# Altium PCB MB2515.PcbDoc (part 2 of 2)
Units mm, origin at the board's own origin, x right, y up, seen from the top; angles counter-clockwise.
Board outline 43 x 51.45 mm, 4 copper layers (Top Layer, Internal 1, Internal 2, Bottom Layer), stack 1.565 mm thick; 100 components, 89 nets, 374 pads, 852 vias.
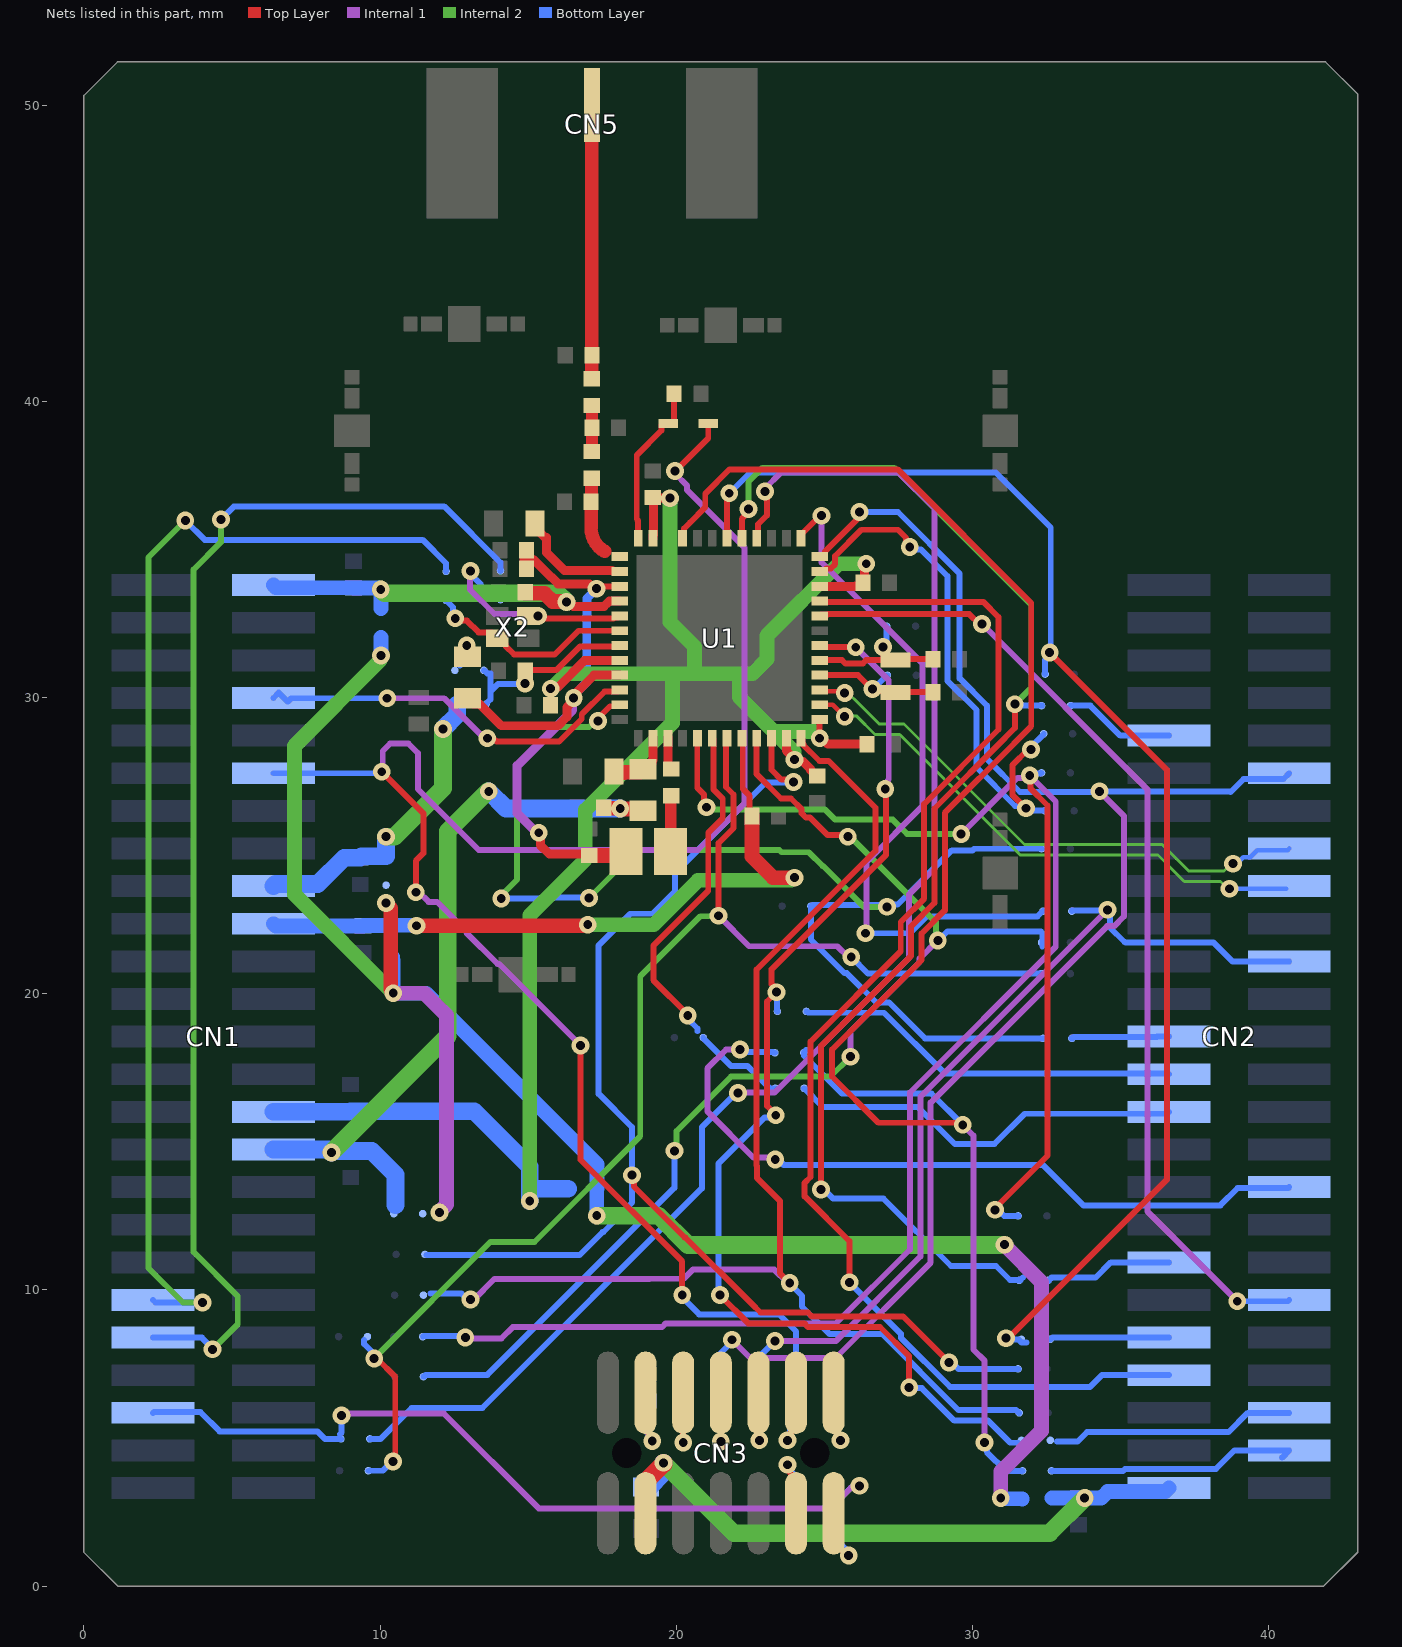
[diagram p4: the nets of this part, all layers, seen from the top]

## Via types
v1: diameter 0.6, hole 0.3, Top Layer to Bottom Layer, tented both sides, 852 vias

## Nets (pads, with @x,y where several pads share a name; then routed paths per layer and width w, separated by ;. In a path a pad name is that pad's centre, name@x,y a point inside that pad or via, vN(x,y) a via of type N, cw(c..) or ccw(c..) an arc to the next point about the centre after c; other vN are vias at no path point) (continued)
GPIO32: CN2.12 R4.2 U1.24 | length 52.4
  Top Layer w0.2: U1.24@24.836,34.753 24.961,34.753 25.011,34.803 25.011,34.925 v1@26.102,36.015
  Internal 1 w0.2: v1(21.88,8.322) 22.497,7.705 25.37,7.705 28.585,10.921 28.585,16.325 34.543,22.283 34.783,22.283 35.105,22.605 35.105,26.007 v1(34.28,26.832)
  Bottom Layer w0.2: R4.2@21.49,7.158 21.49,7.863 21.88,8.253 v1(21.88,8.322) ; v1(26.178,36.264) 27.481,36.264 29.563,34.182 29.563,30.644 30.478,29.729 30.478,27.932 31.6,26.81 34.258,26.81 v1(34.28,26.832) 34.287,26.825 38.68,26.825 38.702,26.802 39.15,27.25 40.496,27.25 CN2.12@40.689,27.443
GPIO33: CN2.29 SB47.1 | length 13.5
  Bottom Layer w0.2: SB47.1@24.311,16.809 24.951,16.17 28.155,16.17 29.4,14.925 30.731,14.925 31.756,15.95 36.562,15.95 CN2.29@36.625,16.013
GPIO34: CN2.41 SB19.2 | length 4
  Bottom Layer w0.2: SB19.2@32.622,8.336 32.634,8.336 32.691,8.393 CN2.41@36.625,8.393
GPIO37: CN1.45 R9.1 SB26.1 | length 27.6
  Internal 1 w0.2: v1(8.7,5.763) 8.762,5.825 12.158,5.825 15.354,2.629 25.199,2.629 25.883,3.313 26.104,3.313 v1(26.18,3.39)
  Bottom Layer w0.2: CN1.45@2.335,5.853 2.365,5.883 3.929,5.883 4.583,5.23 7.879,5.23 8.135,4.973 SB26.1@8.676,4.973 ; 8.645,5.13 8.7,5.185 v1(8.7,5.763) ; R9.1@25.3,2.825 25.395,2.825 25.96,3.39 v1(26.18,3.39)
GPIO38: CN2.22 R5.2 SB33.1 | length 30.1
  Internal 1 w0.2: v1(23.325,8.275) 25.379,8.275 28.235,11.131 28.235,16.513 v1(34.555,22.833)
  Bottom Layer w0.2: R5.2@22.77,7.176 22.814,7.219 22.814,7.763 v1(23.325,8.275) ; SB33.1@33.35,22.8 33.36,22.81 v1@34.432,22.81 ; v1@34.432,22.833 v1(34.555,22.833) 34.632,22.757 34.632,22.237 35.124,21.745 35.141,21.745 35.16,21.725 38.138,21.725 38.769,21.093 CN2.22@40.689,21.093
GPIO39: CN2.25 SB28.1 | length 3.3
  Bottom Layer w0.2: SB28.1@33.35,18.495 33.342,18.503 33.338,18.503 33.35,18.515 33.362,18.503 33.371,18.503 33.41,18.543 36.223,18.543 36.233,18.553 CN2.25@36.625,18.553
GPIO41: CN2.48 SB31.2 | length 8.7
  Bottom Layer w0.2: SB31.2@32.659,3.893 35.079,3.893 35.145,3.96 38.2,3.96 38.21,3.96 38.833,4.583 CN2.48@40.689,4.583 CN2.48@40.447,4.341
GPIO42: CN2.27 SB43.2 | length 13.1
  Bottom Layer w0.2: SB43.2@24.389,19.402 24.401,19.402 24.444,19.359 27.008,19.359 29.056,17.311 36.597,17.311 CN2.27@36.625,17.283
GPIO45: CN2.9 SB24.1 | length 3.7
  Bottom Layer w0.2: SB24.1@33.313,29.725 33.975,29.725 34.987,28.713 CN2.9@36.625,28.713
GPIO46: CN2.34 SB32.2 | length 25.3
  Internal 1 w0.2: v1(22.151,18.114) 21.674,18.114 21.044,17.483 21.044,16.028 22.597,14.475 23.262,14.475 v1(23.337,14.4)
  Bottom Layer w0.2: v1(22.151,18.114) 22.227,18.037 22.465,18.037 22.468,18.035 23.26,18.035 23.276,18.018 23.315,18.018 SB32.2@23.325,18.008 ; v1(23.337,14.4) 23.445,14.4 23.62,14.225 32.368,14.225 33.738,12.855 38.362,12.855 38.947,13.44 40.656,13.44 CN2.34@40.689,13.473
GPIO49: CN2.37 SB29.1 | length 4.3
  Bottom Layer w0.2: SB29.1@32.563,10.325 32.577,10.325 32.667,10.415 34.148,10.415 34.666,10.933 CN2.37@36.625,10.933
GPIO51: CN2.40 U1.20 | length 33.8
  Top Layer w0.2: U1.20@24.836,32.753 24.886,32.803 25.12,32.803 25.128,32.811 29.886,32.811 30.215,32.482 v1(30.32,32.482)
  Internal 1 w0.2: v1(30.32,32.482) 35.9,26.903 35.9,12.653 38.904,9.649 v1@38.921,9.649
  Bottom Layer w0.2: v1(38.934,9.619) 40.645,9.619 CN2.40@40.689,9.663
GPIO54: CN2.43 U1.21 | length 44.5
  Top Layer w0.2: U1.21@24.836,33.253 24.863,33.227 30.361,33.227 30.875,32.712 30.875,28.917 28.363,26.405 28.363,23.212 27.575,22.424 27.575,21.431 24.526,18.382 24.526,13.811 24.331,13.617 24.331,13.161 25.84,11.652 v1(25.84,10.258)
  Bottom Layer w0.2: v1(25.84,10.258) 27.576,8.523 27.576,8.387 29.235,6.728 33.968,6.728 34.363,7.123 CN2.43@36.625,7.123
GPIO55: CN1.8 U1.46 | length 13.4
  Top Layer w0.2: v1(13.619,28.625) 13.695,28.548 13.902,28.548 13.936,28.515 16.045,28.515 16.805,29.276 16.805,29.431 17.578,30.203 18.036,30.203 U1.46@18.086,30.253
  Internal 1 w0.2: v1(10.238,29.975) 12.161,29.975 13.511,28.625 v1(13.619,28.625)
  Bottom Layer w0.2: CN1.8@6.399,29.983 6.578,30.162 6.882,29.857 7,29.975 v1(10.238,29.975)
GPIO56: CN2.46 SB34.2 | length 8.2
  Bottom Layer w0.2: 32.849,4.885 33.543,4.885 33.86,5.202 38.638,5.202 39.29,5.853 CN2.46@40.689,5.853
NetC6_1: C6.1 L4.1 U1.2 | length 2.3
  Top Layer w0.3: L4.1@18.875,27.575 18.975,27.575 19.175,27.775 19.175,27.85 19.211,27.886 U1.2@19.211,28.628
  Top Layer w0.5: C6.1@17.9,27.5 17.95,27.45 17.97,27.47 18.258,27.47 18.263,27.475 18.775,27.475 L4.1@18.875,27.575
NetC7_2: C7.2 D1.1 U1.36 | length 5.6
  Top Layer w0.2: U1.36@18.711,35.378 18.711,35.968 18.661,36.018 18.661,38.18 19.5,39.019 19.5,39.194 19.55,39.244 19.875,39.244 19.925,39.294 C7.2@19.925,40.25
NetC8_1: C8.1 SB38.1 U1.16 X1.2 | length 4.8
  Top Layer w0.2: U1.16@24.836,30.753 26.132,30.753 26.6,30.285 v1(26.62,30.285) ; v1@26.61,30.275 26.66,30.225 27.337,30.225 X1.2@27.398,30.165 ; X1.2@27.398,30.1 X1.2@27.5,30.1 ; X1.2@27.5,30.18 C8.1@28.66,30.18
  Bottom Layer w0.2: v1(26.62,30.285) 26.645,30.285 27.11,30.75 SB38.1@27.125,30.75
NetC9_2: C9.2 SB37.1 U1.17 X1.1 | length 5.3
  Top Layer w0.2: U1.17@24.836,31.253 24.842,31.259 25.592,31.259 25.703,31.148 26.295,31.148 26.406,31.259 X1.1@27.231,31.259 ; v1(26.974,31.702) 26.998,31.679 26.998,31.415 27.153,31.259 X1.1@27.231,31.259 ; C9.2@28.663,31.295 27.428,31.295 27.392,31.259 X1.1@27.231,31.259
  Bottom Layer w0.2: v1(26.974,31.702) 26.974,31.811 27.098,31.935 SB37.1@27.098,32.407
NetC11_2: C11.2 U1.38 | length 3.9
  Top Layer w0.3: C11.2@15.225,35.875 15.225,35.75 15.581,35.394 15.619,35.394 15.619,34.89 16.219,34.29 17.836,34.29 17.873,34.253 U1.38@18.086,34.253
NetC12_1: C12.1 L1.1 U1.37 | length 2.6
  Top Layer w0.45: L1.1@17.15,37.4 17.15,37.385 17.135,37.37 17.135,36.619 C12.1@17.121,36.605 17.121,35.722 ccw(c18.033,35.722) 17.577,34.932
NetC13_2: C13.2 L1.2 L2.1 | length 1.6
  Top Layer w0.4: L2.1@17.145,39.858 17.147,39.856 17.147,39.102 C13.2@17.15,39.1 L1.2@17.15,38.3
NetC14_1: C14.1 CN5.1 L2.2 | length 9.2
  Top Layer w0.45: L2.2@17.145,40.758 17.147,40.761 17.147,41.548 C14.1@17.15,41.55 17.145,41.555 17.145,49.98 17.145,49.995 CN5.1@17.15,50
NetC15_1: C15.1 SB6.2 SB41.1 U1.43 | length 6.6
  Top Layer w0.2: v1(14.891,30.475) 14.896,30.479 14.896,30.899 14.922,30.925 15.95,30.925 16.75,31.725 18.058,31.725 U1.43@18.086,31.753
  Bottom Layer w0.2: SB41.1@13.501,30.917 13.515,30.917 13.615,30.817 13.72,30.817 13.72,30.195 ; SB6.2@13.575,29.775 13.575,29.785 13.72,29.93 13.72,30.195 ; v1(14.891,30.475) 14.878,30.462 13.987,30.462 13.72,30.195
NetC23_2: C23.2 C24.1 C26.1 L6.2 L7.1 U1.39 U1.45 | length 24.2
  Top Layer w0.2: C26.1@14.942,34.351 14.81,34.482 14.81,34.665 ; C24.1@14.942,34.976 14.81,34.844 14.81,34.665 ; 15.168,34.665 14.81,34.665 ; v1(17.308,33.673) 17.416,33.673 17.497,33.753 U1.39@18.086,33.753
  Top Layer w0.3: L7.1@12.95,29.975 13.15,29.775 13.358,29.775 14.086,29.046 16.01,29.046 16.305,29.341 16.305,29.671 16.533,29.899 v1(16.533,29.98) ; 15.168,34.665 15.763,34.07 15.772,34.07 16.005,33.837 17.063,33.837 17.227,33.673 v1(17.308,33.673) ; v1(15.354,25.433) 15.411,25.375 15.411,25.019 15.716,24.714 17.005,24.714 C23.2@17.053,24.666 ; v1@16.489,30.024 17.218,30.753 U1.45@18.086,30.753
  Top Layer w0.5: C23.2@17.053,24.666 18.166,24.666 L6.2@18.3,24.8
  Internal 1 w0.3: v1(15.354,25.433) 15.291,25.433 14.626,26.097 14.626,27.701 16.495,29.57 16.495,29.942 v1(16.533,29.98)
  Bottom Layer w0.3: v1(16.533,29.98) 16.533,30.068 16.975,30.51 16.975,32.773 16.977,32.775 16.977,33.342 v1(17.308,33.673)
NetCN3_4: CN3.4 R2.1 | length 3.2
  Top Layer w0.2: CN3.4@18.96,6.532 19.061,6.431 19.061,5.13 19.184,5.007 v1(19.184,4.902)
  Bottom Layer w0.2: R2.1@18.975,6.258 18.944,6.227 18.944,5.248 19.184,5.007 v1(19.184,4.902)
NetCN3_6: CN3.6 R3.1 | length 3.1
  Top Layer w0.2: v1(20.23,4.85) CN3.6@20.23,6.532
  Bottom Layer w0.2: R3.1@20.211,6.276 20.23,6.257 v1(20.23,4.85)
NetCN3_8: CN3.8 R4.1 | length 3
  Top Layer w0.2: v1(21.5,4.885) CN3.8@21.5,6.532
  Bottom Layer w0.2: R4.1@21.49,6.258 21.5,6.248 v1(21.5,4.885)
NetCN3_10: CN3.10 R5.1 | length 3
  Top Layer w0.2: CN3.10@22.77,6.532 22.785,6.517 22.785,4.94 v1(22.8,4.925)
  Bottom Layer w0.2: R5.1@22.77,6.276 22.8,6.246 v1(22.8,4.925)
NetCN3_11: CN3.11 R6.2 | length 3.1
  Top Layer w0.2: v1(23.755,4.1) 23.83,4.025 23.83,3.841 23.939,3.732 23.939,2.564 CN3.11@24.04,2.462
  Bottom Layer w0.2: v1(23.755,4.1) 23.755,3.994 24.018,3.731 R6.2@24.018,2.875
NetCN3_12: CN3.12 R7.1 | length 3.2
  Top Layer w0.2: v1(23.755,4.925) 23.83,5 23.83,5.153 24.04,5.364 CN3.12@24.04,6.532
  Bottom Layer w0.2: v1(23.755,4.925) 23.83,5 23.83,5.438 24.037,5.645 24.037,6.255 R7.1@24.04,6.258
NetCN3_13: CN3.13 R9.2 | length 2.8
  Top Layer w0.2: CN3.13@25.31,2.462 25.31,1.491 25.762,1.039 v1(25.815,1.039)
  Bottom Layer w0.2: R9.2@25.3,1.925 25.395,1.925 25.545,1.775 25.545,1.415 25.815,1.144 v1(25.815,1.039)
NetCN3_14: CN3.14 R8.1 | length 3.1
  Top Layer w0.2: CN3.14@25.31,6.532 25.411,6.431 25.411,5.157 25.538,5.031 v1(25.538,4.925)
  Bottom Layer w0.2: R8.1@25.31,6.258 25.31,5.259 25.538,5.031 v1(25.538,4.925)
NetL5_1: L5.1 U1.3 | length 1
  Top Layer w0.2: L5.1@19.674,27.596 L5.1@19.711,27.633
  Top Layer w0.3: L5.1@19.711,27.633 U1.3@19.711,28.628
NetL5_2: L5.2 L6.1 | length 1.9
  Top Layer w0.4: L6.1@19.8,24.8 19.812,24.812 19.812,26.671 L5.2@19.824,26.683
NetL7_2: L7.2 SB41.2 | length 1.2
  Top Layer w0.2: v1(12.923,31.757) 12.923,31.402 L7.2@12.95,31.375
  Bottom Layer w0.2: 12.702,31.075 12.702,31.44 12.923,31.661 v1(12.923,31.757)
NetSB1_1: SB1.1 SB2.1 SB3.1 SB4.1 SB5.1 SB36.1 | length 63.4
  Top Layer w0.5: v1(10.2,23.064) 10.2,23.036 10.358,22.879 10.358,20.133 10.444,20.046 v1(10.444,20.019)
  Internal 1 w0.5: v1(10.444,20.019) 10.447,20.017 11.494,20.017 11.86,19.651 12.24,19.271 12.24,12.882 12.001,12.643 v1(12.001,12.616) ; v1(30.95,2.975) 30.95,3.869 32.325,5.244 32.325,10.258 v1@31.079,11.505
  Internal 2 w0.5: v1(10.025,31.415) 10.006,31.396 10.006,31.258 7.11,28.363 7.11,23.353 v1(10.444,20.019)
  Internal 2 w0.6: v1(17.312,12.508) 19.405,12.508 20.395,11.519 31.069,11.519 v1(31.079,11.529)
  Bottom Layer w0.5: v1(10.025,31.415) SB2.1@10.025,32.025 ; 10.413,21.235 10.413,21.154 10.444,21.122 v1(10.444,20.019) 11.547,20.019 17.32,14.247 SB4.1@17.32,13.419 17.31,13.41 17.31,12.554 17.312,12.552 v1(17.312,12.508) ; v1(30.95,2.975) 30.969,2.956 31.664,2.956 SB36.1@31.675,2.945
NetSB7_2: SB7.2 SB8.2 U1.10 | length 44
  Top Layer w0.2: v1(18.5,13.875) 18.564,13.811 18.564,13.49 20.28,11.774 20.304,11.774 22.54,9.538 22.841,9.237 24.444,9.237 24.582,9.099 27.64,9.099 27.649,9.109 v1@29.201,7.558 ; U1.10@23.211,28.628 23.211,27.56 23.543,27.228 23.872,27.228 v1(23.949,27.152)
  Bottom Layer w0.2: SB8.2@11.563,11.175 16.728,11.175 17.511,11.958 17.54,11.958 17.862,12.28 17.862,12.31 18.5,12.947 v1(18.5,13.875) 18.5,15.496 17.375,16.621 17.375,21.635 18.441,22.701 19.204,22.701 19.946,23.444 19.946,24.062 23.017,27.133 23.93,27.133 v1(23.949,27.152) ; v1(29.201,7.548) 29.309,7.548 29.518,7.339 SB7.2@31.55,7.339
NetSB9_2: SB9.2 SB12.2 SB21.2 U1.5 | length 67.7
  Top Layer w0.2: U1.5@20.711,28.628 20.704,28.621 20.704,26.951 20.939,26.716 20.939,26.373 v1(21.016,26.297) ; v1(30.756,12.705) 30.756,12.759 32.53,14.533 32.53,26.353 31.948,26.935 31.948,27.346 v1(31.93,27.365)
  Internal 1 w0.2: v1(12.875,8.393) 12.908,8.36 14.091,8.36 14.476,8.746 19.513,8.746 19.639,8.872 25.39,8.872 27.885,11.367 27.885,16.664 32.805,21.584 32.805,26.49 v1(31.93,27.365) 31.853,27.288 31.51,27.288 v1(29.613,25.391)
  Internal 2 w0.2: v1(21.016,26.297) 21.087,26.225 25.012,26.225 25.36,25.878 27.303,25.878 27.789,25.391 v1(29.613,25.391)
  Bottom Layer w0.2: SB9.2@11.439,8.425 11.45,8.425 11.467,8.442 12.826,8.442 v1(12.875,8.393) ; v1(30.756,12.705) 30.862,12.705 31.067,12.5 SB12.2@31.55,12.5 ; v1(31.93,27.365) 32.005,27.439 32.295,27.439 32.314,27.458 SB21.2@32.326,27.458
NetSB10_1: SB10.1 SB13.1 U1.23 | length 18.8
  Top Layer w0.2: U1.23@24.836,34.253 24.961,34.253 25.061,34.353 25.215,34.353 25.361,34.5 25.361,34.778 26.244,35.661 27.481,35.661 27.752,35.391 27.752,35.073 v1@27.775,35.05 ; v1(31.798,26.26) 31.793,26.26 31.35,26.703 31.35,27.725 31.87,28.245 v1(31.971,28.245)
  Bottom Layer w0.2: v1(27.876,35.077) 27.952,35.001 28.249,35.001 29.149,34.101 29.149,30.564 30.128,29.584 30.128,27.641 31.433,26.337 31.722,26.337 v1(31.798,26.26) 31.875,26.184 32.375,26.184 32.427,26.183 SB10.1@32.438,26.173 ; v1(31.971,28.245) 31.971,28.333 32.401,28.763 SB13.1@32.401,28.775
NetSB14_2: SB14.2 SB17.2 U1.9 | length 39.3
  Top Layer w0.2: U1.9@22.711,28.628 22.711,27.411 23.533,26.59 23.868,26.59 24.227,26.231 24.227,26.092 24.374,25.945 24.513,25.945 25.107,25.352 25.736,25.352 v1(25.787,25.301)
  Internal 1 w0.2: v1(25.875,17.875) 25.875,18.733 28.208,21.066 28.208,21.183 v1(28.825,21.8)
  Internal 2 w0.2: v1(19.932,14.697) 20.006,14.771 20.006,15.362 21.848,17.204 25.204,17.204 v1(25.875,17.875) ; v1(25.787,25.301) 25.874,25.301 28.76,22.415 28.76,21.865 v1(28.825,21.8)
  Bottom Layer w0.2: SB14.2@11.463,7.076 11.478,7.076 11.535,7.134 13.619,7.134 19.932,13.447 v1(19.932,14.697) ; v1@28.837,21.787 29.149,22.099 32.305,22.099 32.35,22.054 32.35,21.6
NetSB16_2: SB16.2 SB18.2 U1.12 | length 44.3
  Top Layer w0.2: v1(23.827,10.235) 23.493,10.569 23.493,13.01 22.728,13.775 22.728,14.189 22.711,14.206 22.711,20.818 26.719,24.825 26.719,26.277 25.141,27.855 24.828,27.855 24.286,28.397 24.286,28.428 24.261,28.453 24.261,28.578 U1.12@24.211,28.628
  Internal 1 w0.2: v1(13.05,9.675) 13.158,9.675 13.86,10.377 19.099,10.377 19.101,10.38 20.249,10.38 20.555,10.686 23.305,10.686 23.755,10.235 v1(23.827,10.235)
  Bottom Layer w0.2: 11.705,9.875 12.744,9.875 12.944,9.675 v1(13.05,9.675) ; v1(23.827,10.235) 23.827,10.218 24.243,9.802 24.243,9.438 25.164,8.517 26.948,8.517 29.523,5.943 31.47,5.943 31.56,5.853 SB18.2@31.572,5.853
NetSB19_1: SB19.1 SB22.1 U1.30 | length 46.3
  Top Layer w0.2: U1.30@21.711,35.378 21.711,36.822 v1(21.784,36.895) ; v1(31.129,8.374) 31.199,8.374 36.565,13.74 36.565,27.55 v1(32.6,31.515)
  Bottom Layer w0.2: v1@21.795,36.895 22.5,37.6 30.774,37.6 32.637,35.737 32.637,31.552 v1(32.6,31.515) 32.6,31.424 32.439,31.263 SB22.1@32.439,30.79 ; v1(31.129,8.374) 31.17,8.332 31.543,8.332 31.645,8.23 31.823,8.23
NetSB23_2: SB23.2 SB28.2 SB30.2 U1.47 | length 42.6
  Top Layer w0.2: v1(17.355,29.203) 17.355,29.301 17.758,29.703 18.036,29.703 U1.47@18.086,29.753
  Internal 2 w0.2: v1(14.089,23.213) 14.089,23.317 14.626,23.854 14.626,27.701 15.931,29.006 17.05,29.006 17.247,29.203 v1(17.355,29.203) ; v1(17.053,23.234) 18.67,24.851 23.472,24.851 23.546,24.776 24.471,24.776 24.937,24.31 24.953,24.31 26.329,22.933 v1(27.11,22.933)
  Bottom Layer w0.2: v1(14.089,23.213) 14.094,23.208 15.526,23.208 ; 15.526,23.248 17.039,23.248 v1(17.053,23.234) ; SB23.2@32.348,24.894 30.055,24.894 30.002,24.841 29.298,24.841 27.467,23.01 27.187,23.01 v1(27.11,22.933) 27.043,23.001 24.599,23.001 24.558,22.96 SB30.2@24.543,22.96 24.543,21.825 25.674,20.695 25.752,20.695 26.737,19.709 27.175,19.709 28.39,18.495 SB28.2@32.375,18.495
NetSB24_2: SB24.2 SB29.2 U1.29 | length 45.4
  Top Layer w0.2: U1.29@22.211,35.378 22.211,36.03 22.436,36.255 v1(22.436,36.361) ; v1(24.881,13.389) 24.881,17.445 24.876,17.451 24.876,18.229 27.925,21.278 27.925,22.279 28.713,23.067 28.713,26.25 31.071,28.608 31.071,28.618 31.425,28.972 v1(31.425,29.775)
  Internal 2 w0.2: v1(22.436,36.361) 22.436,37.283 22.903,37.75 27.35,37.75 31.98,33.12 31.98,30.33 v1(31.425,29.775)
  Bottom Layer w0.2: v1(24.881,13.389) 24.99,13.389 25.293,13.085 26.991,13.085 29.269,10.807 30.786,10.807 31.259,10.335 31.578,10.335 31.588,10.325 31.602,10.325 31.702,10.425 ; v1(31.425,29.775) 31.467,29.733 32.329,29.733 SB24.2@32.338,29.725
NetSB26_2: SB26.2 U1.28 | length 50
  Top Layer w0.2: U1.28@22.711,35.378 22.756,35.423 22.756,35.847 23.053,36.144 23.053,36.894 v1(22.991,36.955)
  Internal 1 w0.2: v1(22.075,16.654) 22.09,16.668 23.316,16.668 27.858,21.211 27.858,23.355 28.713,24.21 28.713,36.387 27.51,37.59 23.528,37.59 22.991,37.053 v1(22.991,36.955)
  Bottom Layer w0.2: SB26.2@9.651,4.973 10.018,4.973 11.063,6.018 13.449,6.018 20.861,13.43 20.861,15.494 22.021,16.654 v1(22.075,16.654)
NetSB31_1: SB31.1 SB32.1 U1.33 | length 58.3
  Top Layer w0.2: U1.33@20.211,35.378 20.261,35.428 20.261,35.707 20.458,35.903 20.459,35.903 20.975,36.419 20.975,36.88 21.795,37.7 27.47,37.7 31.98,33.19 31.98,29.032 31.421,28.473 31.421,28.463 29.063,26.105 29.063,22.816 28.275,22.028 28.275,21.133 25.254,18.112 25.254,17.206 26.816,15.645 29.595,15.645 v1(29.665,15.575)
  Internal 1 w0.2: v1(29.665,15.575) 30.025,15.215 30.025,7.992 30.404,7.613 v1(30.404,4.85)
  Bottom Layer w0.2: SB32.1@24.375,18.097 24.3,18.022 SB32.1@24.3,18.008 24.31,17.997 24.31,17.907 25.584,16.634 28.606,16.634 v1(29.665,15.575) ; v1(30.404,4.85) 30.478,4.775 30.478,4.528 31.113,3.893 SB31.1@31.684,3.893
NetSB33_2: SB33.2 U1.25 | length 23.7
  Top Layer w0.2: U1.25@24.211,35.378 24.211,35.503 24.846,36.138 v1(24.9,36.138)
  Internal 1 w0.2: v1(24.9,36.138) 24.9,34.561 28.302,31.16 28.302,26.329 26.421,24.449 26.421,22.083 v1(26.38,22.043)
  Bottom Layer w0.2: v1(26.38,22.043) 27.886,22.043 28.457,22.614 32.189,22.614 SB33.2@32.375,22.8
NetSB34_1: SB34.1 SB43.1 U1.18 | length 39.9
  Top Layer w0.2: v1(21.471,9.83) 21.471,9.827 22.426,8.872 24.314,8.872 24.437,8.749 26.876,8.749 27.858,7.767 v1(27.858,6.708) ; v1(23.353,15.9) 23.353,15.926 23.061,16.217 23.061,19.736 23.375,20.049 23.375,20.161 23.217,20.319 23.217,20.828 27.069,24.68 27.069,26.89 v1(27.05,26.909) ; U1.18@24.836,31.753 24.884,31.706 v1@26.048,31.706
  Internal 1 w0.2: v1(26.056,31.698) 27.17,30.584 27.17,27.226 27.127,27.183 27.127,26.985 v1(27.05,26.909)
  Bottom Layer w0.2: v1(21.471,9.83) 21.425,9.876 21.425,14.274 22.978,15.827 23.279,15.827 v1(23.353,15.9) ; v1(23.375,20.053) 23.401,20.027 23.401,19.415 SB43.1@23.414,19.402 ; v1(27.858,6.708) 27.88,6.686 28.284,6.686 29.382,5.589 30.522,5.589 31.267,4.844 31.541,4.844
NetSB39_1: SB39.1 U1.42 X2.1 | length 7.2
  Top Layer w0.2: v1(12.535,32.672) 12.612,32.596 12.929,32.596 13.325,32.2 13.75,32.2 X2.1@13.95,32 14.025,32 14.225,31.8 14.225,31.746 14.521,31.45 15.891,31.45 16.694,32.253 U1.42@18.086,32.253
  Bottom Layer w0.2: SB39.1@12.225,33.282 12.461,33.046 12.461,32.747 v1(12.535,32.672)
NetSB40_1: SB40.1 U1.41 X2.3 | length 7.6
  Top Layer w0.2: v1(15.324,32.75) 15.401,32.673 15.637,32.673 15.641,32.669 17.877,32.669 17.911,32.703 18.036,32.703 U1.41@18.086,32.753
  Internal 1 w0.2: v1(13.051,34.27) 13.035,34.254 13.035,33.642 13.862,32.816 15.258,32.816 v1(15.324,32.75)
  Bottom Layer w0.2: v1(13.051,34.27) 13.051,34.161 13.41,33.802 13.41,33.737 13.682,33.465 13.883,33.465 14.048,33.3 SB40.1@14.063,33.3
NetSB44_2: SB44.2 SB45.2 SB48.2 U1.7 | length 44.6
  Top Layer w0.2: v1(9.798,7.689) 9.893,7.689 10.509,7.073 10.509,4.285 v1(10.434,4.21) ; v1(21.425,22.632) 21.426,25.088 21.927,25.59 21.927,26.725 21.674,26.978 21.674,28.591 U1.7@21.711,28.628
  Internal 1 w0.2: v1(21.425,22.632) 22.453,21.604 25.434,21.604 25.793,21.245 v1(25.901,21.245)
  Internal 2 w0.2: v1(9.798,7.689) 9.798,7.697 13.721,11.621 15.209,11.621 18.78,15.191 18.78,20.586 20.81,22.616 21.409,22.616 v1(21.425,22.632)
  Bottom Layer w0.2: 9.457,8.314 9.457,8.18 9.798,7.839 v1(9.798,7.689) ; SB44.2@9.604,3.898 10.094,3.898 10.406,4.21 v1(10.434,4.21) ; v1(25.901,21.245) 26.468,20.678 SB48.2@32.311,20.678
NetSB46_2: SB46.2 SB47.2 U1.6 | length 14.8
  Top Layer w0.2: v1(20.384,19.265) 20.384,19.297 19.221,20.461 19.221,21.62 21.076,23.475 21.076,25.435 21.566,25.925 21.566,26.584 21.25,26.9 21.25,28.59 U1.6@21.211,28.628
  Bottom Layer w0.2: v1(20.384,19.265) 20.384,19.157 20.713,18.829 20.713,18.735 ; SB46.2@20.907,18.52 20.907,18.495 21.838,17.564 22.398,17.564 23.152,16.809 SB47.2@23.336,16.809
NRST: CN1.12 D1.2 R7.2 | length 62
  Top Layer w0.2: v1(10.054,27.493) 11.46,26.087 11.46,24.743 11.205,24.488 v1(11.205,23.425) ; v1(16.766,18.257) 16.766,14.397 20.196,10.967 v1(20.196,9.83) ; v1(19.951,37.65) 19.974,37.65 21.075,38.751 D1.2@21.075,39.244
  Internal 1 w0.2: v1(10.054,27.493) 10.087,27.527 10.087,28.193 10.338,28.444 10.954,28.444 11.276,28.122 11.276,26.904 13.329,24.851 20.729,24.851 22.304,26.426 22.304,35.055 20.361,36.997 20.361,37.149 19.951,37.56 v1(19.951,37.65) ; v1(11.205,23.425) 11.313,23.425 11.637,23.102 11.92,23.102 12.907,22.116 12.907,22.061 13.961,21.007 14.015,21.007 v1(16.766,18.257)
  Bottom Layer w0.2: CN1.12@6.399,27.443 10.004,27.443 v1(10.054,27.493) ; v1(20.196,9.83) 20.196,9.75 20.769,9.177 23.466,9.177 24.04,8.603 R7.2@24.04,7.158
OSC_IN: CN1.39 SB39.2 | length 39.4
  Internal 2 w0.2: v1(3.425,35.975) 2.175,34.725 2.175,10.743 3.343,9.575 v1(4,9.575)
  Bottom Layer w0.2: CN1.39@2.335,9.663 2.423,9.575 v1(4,9.575) ; v1(3.425,35.975) 4.08,35.32 11.435,35.32 12.225,34.53 SB39.2@12.225,34.257
OSC_OUT: CN1.41 SB40.2 | length 42.3
  Internal 2 w0.2: v1(4.345,7.996) 5.193,8.844 5.193,9.793 3.7,11.286 3.7,34.315 4.624,35.24 v1(4.624,36.008)
  Bottom Layer w0.2: CN1.41@2.335,8.393 3.982,8.393 4.354,8.022 4.354,8.005 v1(4.345,7.996) ; v1(4.624,36.008) 5.057,36.441 5.181,36.441 5.193,36.452 12.162,36.452 14.063,34.552 SB40.2@14.063,34.275
USB_FS_N: CN2.18 U1.14 | length 18.3
  Top Layer w0.155: U1.14@24.836,29.753 25.282,29.753 v1(25.68,29.355)
  Internal 2 w0.1: v1(25.68,29.355) 25.708,29.383 26.071,29.383 26.702,28.752 27.536,28.752 31.604,24.684 36.255,24.684 37.147,23.792 38.371,23.792 38.62,23.543 v1(38.675,23.543)
  Bottom Layer w0.155: v1(38.675,23.543) CN2.18@40.59,23.543
USB_FS_P: CN2.16 U1.15 | length 18.7
  Top Layer w0.155: U1.15@24.836,30.253 24.885,30.204 25.631,30.204 v1(25.68,30.155)
  Internal 2 w0.1: v1(25.68,30.155) 25.794,30.155 26.136,29.813 26.847,29.102 27.681,29.102 31.749,25.034 36.4,25.034 37.292,24.142 38.488,24.142 38.738,24.391 v1(38.793,24.391)
  Bottom Layer w0.155: v1(38.793,24.391) 38.913,24.391 39.134,24.612 39.37,24.612 39.603,24.845 40.631,24.845 CN2.16@40.689,24.903
VDD1: C2.2 C10.1 CN1.2 SB2.2 U1.40 | length 14.3
  Top Layer w0.2: U1.40@18.075,33.242 U1.40@18.086,33.253 U1.40@18.081,33.248
  Top Layer w0.3: v1(16.294,33.223) 16.375,33.223 16.525,33.073 17.557,33.073 17.687,33.203 17.692,33.203 17.742,33.253 U1.40@18.081,33.253
  Top Layer w0.5: C10.1@14.9,33.55 14.9,33.525 14.905,33.52 15.544,33.52 15.822,33.242 16.275,33.242 v1(16.294,33.223)
  Internal 2 w0.6: v1(10.022,33.641) 10.143,33.52 15.997,33.52 v1(16.294,33.223)
  Bottom Layer w0.5: CN1.2@6.399,33.793 6.487,33.705 9.095,33.705 9.105,33.695 9.94,33.695 9.995,33.641 v1(10.022,33.641) ; SB2.2@10.025,33 v1@10.025,33.637
VDD3: C3.2 CN1.18 SB3.2 SB6.1 | length 10.5
  Internal 2 w0.6: v1(10.2,25.301) 10.485,25.301 12.119,26.935 v1(12.119,28.933)
  Bottom Layer w0.6: CN1.18@6.399,23.633 6.468,23.702 7.896,23.702 8.786,24.592 C3.2@9.329,24.592 9.375,24.638 SB3.2@10.2,24.638 v1(10.2,25.301) ; v1(12.119,28.933) 12.6,29.414 SB6.1@12.6,29.775
VDD4: C4.2 C16.1 C17.1 C18.1 C19.1 C28.1 CN1.30 SB4.2 U1.11 U1.13 U1.22 U1.35 U1.44 | length 66.5
  Top Layer w0.2: v1(24.836,28.625) U1.13@24.836,29.253
  Top Layer w0.3: v1@16.007,30.355 16.905,31.253 U1.44@18.086,31.253 ; U1.35@19.211,35.378 19.211,35.458 19.228,35.475 19.228,36.753 19.241,36.74 19.77,36.74 v1(19.781,36.729) ; U1.11@23.711,28.628 23.711,28.202 23.985,27.928 v1(23.985,27.901) ; v1@24.271,27.843 24.523,27.591 24.523,27.559 24.732,27.35 C16.1@24.757,27.35 ; v1(24.836,28.625) 24.917,28.625 25.116,28.426 C28.1@26.434,28.426 ; U1.22@24.836,33.753 26.019,33.753 26.036,33.77 26.195,33.77 C17.1@26.3,33.875 26.355,33.93 26.355,34.458 v1(26.41,34.513)
  Internal 2 w0.2: v1(15.755,30.298) v1@15.802,30.298
  Internal 2 w0.5: v1(15.051,13) 15.051,22.65 16.927,24.526 16.927,26.197 19.87,29.141 19.87,30.802 ; v1@15.802,30.298 15.802,30.317 16.286,30.802 19.87,30.802 ; v1(19.781,36.729) 19.781,32.552 20.614,31.718 20.614,30.802 ; v1(23.985,27.901) 23.966,27.92 23.966,28.176 23.289,28.853 ; v1(24.836,28.625) 24.836,28.652 24.673,28.816 24.673,28.853 23.289,28.853 ; v1(26.41,34.513) 25.478,34.513 23.059,32.094 23.059,31.286 22.574,30.802 22.131,30.802 ; 19.87,30.802 20.614,30.802 ; 20.614,30.802 22.131,30.802 ; 22.131,30.802 22.131,30.011 23.289,28.853
  Bottom Layer w0.6: CN1.30@6.399,16.013 8.978,16.013 C4.2@9.001,16.036 13.175,16.036 15.05,14.161 v1(15.051,13) ; 15.184,13.419 SB4.2@16.345,13.419
VDD5: C5.2 C21.1 CN1.32 L4.2 SB5.2 | length 26.1
  Top Layer w0.5: C21.1@17.55,26.275 17.55,26.268 17.555,26.263 v1@18.092,26.263 ; v1(18.104,26.25) v1@18.092,26.263 ; L4.2@18.875,26.175 18.819,26.231 18.123,26.231 v1@18.092,26.263
  Internal 2 w0.6: v1(8.355,14.642) 12.284,18.571 12.284,25.481 13.635,26.832 v1(13.665,26.832)
  Bottom Layer w0.6: CN1.32@6.399,14.743 8.355,14.743 v1(8.355,14.642) 8.402,14.689 C5.2@9.005,14.689 ; C5.2@9.018,14.692 9.719,14.692 10.521,13.89 10.521,12.866 ; v1(13.665,26.832) 14.247,26.25 v1(18.104,26.25)
VDD14: C22.2 C27.2 CN2.49 CN3.3 SB36.2 | length 22.9
  Top Layer w0.6: CN3.3@18.96,2.462 18.96,3.525 19.561,4.126 v1(19.561,4.166)
  Internal 2 w0.6: v1(19.561,4.166) 21.938,1.789 32.591,1.789 v1(33.782,2.98)
  Bottom Layer w0.5: SB36.2@32.681,2.975 C27.2@33.575,2.975 33.58,2.98 34.341,2.98 34.555,3.195 36.507,3.195 CN2.49@36.625,3.313
  Bottom Layer w0.6: C22.2@18.975,3.35 19.1,3.35 19.561,3.811 v1(19.561,4.166)
VDDA: C1.2 C20.2 CN1.20 SB1.2 U1.8 | length 24.2
  Top Layer w0.2: U1.8@22.211,28.628 22.239,28.6 22.239,26.915 22.472,26.682 22.472,26.078 C20.2@22.55,26
  Top Layer w0.5: v1(11.229,22.293) 16.942,22.293 16.98,22.331 v1(17.007,22.331) ; C20.2@22.55,26 22.555,25.995 22.555,24.629 23.266,23.918 v1(23.992,23.918)
  Internal 2 w0.5: v1@17.034,22.331 19.236,22.331 20.733,23.829 23.875,23.829 23.965,23.918 v1(23.992,23.918)
  Bottom Layer w0.5: CN1.20@6.399,22.363 6.474,22.288 9.417,22.288 9.427,22.298 10.348,22.298 SB1.2@10.413,22.364 10.464,22.312 11.21,22.312 v1(11.229,22.293)
pads on no net: CN1.3 CN1.4 CN1.5 CN1.10 CN1.11 CN1.16 CN1.19 CN1.21 CN1.23 CN1.27 CN1.43 CN1.48 CN1.50 CN2.1 CN2.3 CN2.4 CN2.5 CN2.6 CN2.17 CN2.19 CN2.24 CN2.28 CN2.30 CN2.31 CN2.33 CN2.36 CN2.47 CN3.1 CN3.2 CN3.9 CN3.NPTH1 CN3.NPTH2 U1.19 U1.31 U1.32 U1.48

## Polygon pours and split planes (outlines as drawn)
GND on Bottom Layer "Bottom Layer-GND" (solid, remove dead copper, pour order 7): -5.722,60.183 47.45,60.183 47.45,-6.633 -5.722,-6.633
GND on Top Layer "Top Layer-GND" (solid, remove dead copper, pour order 9): -0.984,56.842 44.025,56.842 44.025,-1.8 -0.984,-1.8
GND on Internal 2 "Internal 2-GND" (solid, remove dead copper, pour order 11): -6.863,54.407 46.703,54.407 46.703,-2.025 -6.863,-2.025
GND on Internal 1 "GND_L02_P016" (solid, remove dead copper, pour order 16): 18.5,52.219 18.5,34.43 15.86,34.43 15.86,52.219 -1.639,52.219 -1.639,-2.225 44.069,-2.225 45.097,-0.949 45.097,-0.533 45.097,52.219

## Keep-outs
Top Layer:
  rectangle: 16.907,40.223 17.392,40.384
  rectangle: 16.912,37.765 17.397,37.926
  rectangle: 18.61,29.16 24.299,34.848
Keep-Out Layer:
  lines w0.1: 43.001,1.145 43.001,39.986 43.001,50.374 41.925,51.45 1.127,51.45 0.001,50.324 0.001,1.143 1.139,0.005 41.852,0.005 42.505,0.652 43.002,1.145

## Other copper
Top Layer:
  region net NetC12_1: 17.699,35.121 18.079,34.903 18.361,34.903 18.361,34.603 17.811,34.603 17.498,34.721 17.489,34.724
  text "1" at 10.365,1.475 h0.81
Internal 1:
  text "2" at 10.91,1.475 h0.81
Internal 2:
  text "3" at 11.59,1.484 h0.81
Bottom Layer:
  text "4" at 12.616,1.475 h0.81
Multi-Layer:
  pour cut-out: 10.149,2.2 10.147,1.375 12.802,1.375 12.802,2.2

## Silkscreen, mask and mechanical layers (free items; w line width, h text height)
Top Overlay:
  lines w0.05: -0.591,0.005 1.139,0.005 ; 0.001,-0.496 0.001,1.143
  lines w0.1: 19.401,26.144 19.572,26.001 ; 19.551,26.322 19.408,26.152 20.14,26.152 ; 10.149,1.325 12.775,1.325 12.775,2.2 10.149,2.2 10.149,1.325
  lines w0.15: 9.077,20.65 30.977,20.65 30.977,42.607 9.077,42.607 9.077,20.65
  text "J" at 1.575,47.57 h7.62
  text "K" at 1.325,42.527 h7.62
  text "MB2515A" at 1.101,1.405 h2.5
Bottom Overlay:
  drawing of 200 lines, arcs and shapes, not listed
  text "Layer" at -15.37,133.178 h1.52
  text "Name" at -8.992,133.178 h1.52
  text "Material" at 3.342,133.178 h1.52
  text "Thickness" at 14.425,133.178 h1.52
  text "Constant" at 23.529,133.178 h1.52
  text "Board Layer Stack" at 31.955,133.178 h1.52
  text "Top Overlay" at -8.992,130.13 h1.52
  text "Top Solder" at -8.992,127.082 h1.52
  text "Solder Resist" at 3.342,127.082 h1.52
  text "0.018mm" at 14.425,127.082 h1.52
  text "4.2" at 23.529,127.082 h1.52
  text "1" at -15.37,124.034 h1.52
  text "Top Layer" at -8.992,124.034 h1.52
  text "0.041mm" at 14.425,124.034 h1.52
  text "Dielectric 1" at -8.992,120.986 h1.52
  text "FR-4" at 3.342,120.986 h1.52
  text "0.076mm" at 14.425,120.986 h1.52
  text "3.7" at 23.529,120.986 h1.52
  text "2" at -15.371,117.938 h1.52
  text "Internal 1" at -8.992,117.938 h1.52
  text "0.030mm" at 14.425,117.938 h1.52
  text "Dielectric 3" at -8.992,114.89 h1.52
  text "FR-4" at 3.342,114.89 h1.52
  text "1.270mm" at 14.425,114.89 h1.52
  text "4.5" at 23.529,114.89 h1.52
  text "3" at -15.37,111.842 h1.52
  text "Internal 2" at -8.992,111.842 h1.52
  text "0.030mm" at 14.425,111.842 h1.52
  text "Dielectric 2" at -8.992,108.794 h1.52
  text "FR-4" at 3.342,108.794 h1.52
  text "0.076mm" at 14.425,108.794 h1.52
  text "3.7" at 23.529,108.794 h1.52
  text "4" at -15.37,105.746 h1.52
  text "Bottom Layer" at -8.992,105.746 h1.52
  text "0.041mm" at 14.425,105.746 h1.52
  text "Bottom Solder" at -8.992,102.698 h1.52
  text "Solder Resist" at 3.342,102.698 h1.52
  text "0.018mm" at 14.425,102.698 h1.52
  text "4.2" at 23.529,102.698 h1.52
  text "Bottom Overlay" at -8.992,99.65 h1.52
  text "Total board thickness:" at -15.37,96.602 h1.52
  text "1.600mm" at 14.425,96.602 h1.52
  text "H" at 40.9,46.95 h7.62
  text "G" at 34.341,46.58 h7.62
  text "I" at 5.611,46.4 h7.62
Top Solder:
  lines w0.1: 9.015,36.629 9.025,36.629 ; 18.361,20.621 18.361,20.624
  lines w0.5: 8.992,41.562 8.992,42.625 15.431,42.625 ; 9.066,28.177 9.066,36.452 ; 11.107,20.645 11.982,20.658 ; 17.103,20.676 18.28,20.676 ; 23.992,42.568 30.912,42.568 30.912,41.491 ; 29.065,20.624 30.95,20.624 30.95,21.462 ; 30.912,35.3 30.912,36.525 ; 30.914,27.496 30.932,26.59
M1-Board Shape:
  lines w0.1: 0.001,50.3 0.001,1.143 1.139,0.005 41.852,0.005 43.002,1.145 43.001,39.986 43.001,50.35 ; 0.001,50.324 1.132,51.455 41.913,51.455 43.001,50.367
M4-Bottom Dimensions:
  lines w0.1: 2.335,-4.995 2.335,33.793 39.969,33.793 ; 36.625,-4.995 36.625,33.793
  lines w0.254: 2.399,-5.229 2.399,-4.721 ; 3.923,-5.483 2.399,-4.975 ; 3.923,-4.467 2.399,-4.975 ; 12.282,-4.975 2.399,-4.975 ; 26.807,-4.975 36.689,-4.975 ; 35.165,-5.483 36.689,-4.975 ; 35.165,-4.467 36.689,-4.975 ; 36.689,-5.229 36.689,-4.721
  text "34.29 (mm)" at 12.536,-5.889 h1.52
  text "CN1/CN2 spacing" at 12.49,-7.188 h0.81
M14-Top Assembly:
  lines w0.01: 14.4,55.45 19.9,55.45 ; 14,56.2 20.3,56.6 ; 14,56.2 14.4,56.6 ; 14,56.2 14.4,55.8 ; 14,56.2 14,59.4 ; 14,57 20.3,57.4 ; 14,57 14.4,56.6 ; 14,57 14.4,57.4 ; 14,57.8 20.3,58.2 ; 14,57.8 14.4,57.4 ; 14,57.8 14.4,58.2 ; 14,58.6 20.3,59 ; 14,58.6 14.4,58.2 ; 14,58.6 14.4,59 ; 14,59.4 14.4,59 ; 14,59.4 14.4,59.425 20.3,59.8 ; 14,59.4 14.4,59.8 ; 14.25,52.9 20.05,52.9 ; 14.25,52.9 12.35,52.9 12.35,46.5 13.45,46.5 13.45,51.25 20.85,51.25 20.85,46.5 21.95,46.5 21.95,52.9 20.05,52.9 ; 14.25,52.9 14.4,53.05 ; 14.4,53.05 19.9,53.05 ; 14.4,53.05 14.4,55.8 ; 14.4,55.8 14.4,59.8 ; 14.4,55.8 19.9,56.2 ; 14.4,56.6 19.9,57 ; 14.4,57.4 19.9,57.8 ; 14.4,58.2 19.9,58.6 ; 14.4,59 19.9,59.4 ; 14.4,59.8 19.9,60.2 ; 14.4,59.8 14.4,60.725 14.475,60.8 19.825,60.8 19.9,60.725 19.9,60.2 ; 19.9,53.05 19.9,56.2 ; 19.9,53.05 20.05,52.9 ; 19.9,56.2 19.9,60.2 ; 19.9,56.2 20.3,56.6 ; 19.9,57 20.3,57.4 ; 19.9,57 19.9,57 ; 19.9,57 20.3,56.6 ; 19.9,57.8 20.3,58.2 ; 19.9,57.8 20.3,57.4 ; 19.9,58.6 20.3,59 ; 19.9,58.6 20.3,58.2 ; 19.9,59.4 20.3,59.8 ; 19.9,59.4 20.3,59 ; 19.9,60.2 20.3,59.8 ; 20.3,56.6 20.3,59.8
M15-Bottom Assembly:
  text "C2" at 8.826,33.934 h0.8 r270
Drill Drawing:
  lines w0.254: -15.819,76.317 -14.417,76.317 -14.417,77.718 -15.819,77.718 -15.819,76.317 ; -15.819,79.821 -15.468,79.821 -15.468,79.471 -14.767,79.471 -14.767,79.821 -14.417,79.821 -14.417,80.522 -14.767,80.522 -14.767,80.873 -15.468,80.873 -15.468,80.522 -15.819,80.522 -15.819,79.821
  lines w0.381: -17.09,75.37 115.339,75.37 ; -17.09,81.679 115.339,81.679 ; -8.983,72.216 -8.983,84.833 ; -1.555,72.216 -1.555,84.833 ; 12.36,72.216 12.36,84.833 ; 18.645,72.216 18.645,84.833 ; 27.797,72.216 27.797,84.833 ; 45.14,72.216 45.14,84.833 ; 52.638,72.216 52.638,84.833 ; 62.434,72.216 62.434,84.833 ; 74.368,72.216 74.368,84.833 ; 84.206,72.216 84.206,84.833 ; 99.505,72.216 99.505,84.833 ; -17.09,72.216 115.339,72.216 115.339,84.833 -17.09,84.833 -17.09,72.216
  text "Symbol" at -15.197,82.625 h1.83
  text "Count" at -8.037,82.625 h1.83
  text "Hole Size" at -0.608,82.625 h1.83
  text "Plated" at 13.306,82.625 h1.83
  text "Hole Type" at 19.592,82.625 h1.83
  text "Drill Layer Pair" at 28.743,82.625 h1.83
  text "Via/Pad" at 46.086,82.625 h1.83
  text "Pad Shape" at 53.585,82.625 h1.83
  text "Template" at 63.38,82.625 h1.83
  text "Description" at 75.314,82.625 h1.83
  text "Hole Tolerance (+)" at 85.152,82.625 h1.83
  text "Hole Tolerance (-)" at 100.451,82.625 h1.83
  text "2" at -8.037,79.471 h1.52
  text "1.000mm (39.37mil)" at -0.608,79.471 h1.52
  text "NPTH" at 13.306,79.471 h1.52
  text "Round" at 19.592,79.471 h1.52
  text "Top Layer - Bottom Layer" at 28.743,79.471 h1.52
  text "Pad" at 46.086,79.471 h1.52
  text "Rounded" at 53.585,79.471 h1.52
  text "c0hn100m105p0" at 63.38,79.471 h1.52
  text "852" at -8.037,76.317 h1.52
  text "0.300mm (11.81mil)" at -0.608,76.317 h1.52
  text "PTH" at 13.306,76.317 h1.52
  text "Round" at 19.592,76.317 h1.52
  text "Top Layer - Bottom Layer" at 28.743,76.317 h1.52
  text "Via" at 46.086,76.317 h1.52
  text "Rounded" at 53.585,76.317 h1.52
  text "(Mixed)" at 63.38,76.317 h1.52
  text "854 Total" at -8.037,73.162 h1.52

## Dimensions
17.15,62.475 to 43.001,50.35 on M2-Board Dimensions
17.15,50 to 0.001,50.3 on M2-Board Dimensions
0.001,-0.496 to 43.002,0 on M2-Board Dimensions
1.139,0.005 to 1.127,51.45 on M2-Board Dimensions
